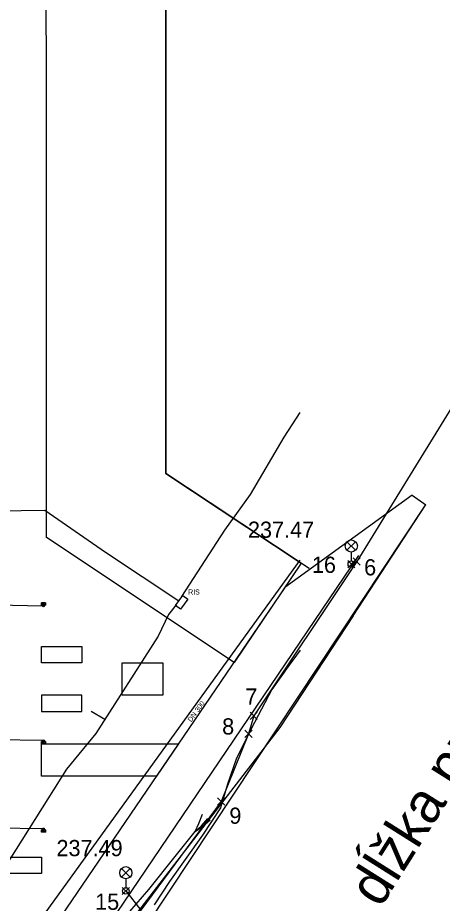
# Model space of a CAD drawing. Extents: x -263861 to -263441, y -1242367 to -1242070.
# Drawn here: x -263784.9 to -263732.4, y -1242254.1 to -1242144.8 of the extents above; entities that cross this region are included whole.
import ezdxf

# ---------------------------------------------------------------- set-up
doc = ezdxf.new("R2010")
doc.units = 0
for name, color, linetype in [('KFA_BODY', 7, 'Continuous'), ('KFA_JESTV_IS_DSP', 7, 'Continuous'), ('KFA_SITUACIA_DSP', 7, 'Continuous'), ('KFA_VO_prelozka_pri_vjazde_do KFA_LAMPA', 7, 'Continuous'), ('KFA_VO_prelozka_pri_vjazde_do KFA_TRASA', 7, 'Continuous'), ('POPIS', 7, 'Continuous')]:
    doc.layers.add(name, color=color, linetype=linetype)

msp = doc.modelspace()

# ---------------------------------------------------------------- linework, layer by layer
at = {"layer": 'KFA_BODY'}
for p, q in [((-263744.11, -1242212.66), (-263743.23, -1242211.78)), ((-263743.23, -1242212.66), (-263744.11, -1242211.78)), ((-263743.43, -1242212.34), (-263742.55, -1242211.45)), ((-263742.55, -1242212.34), (-263743.43, -1242211.45)), ((-263743.67, -1242212.22), (-263742.99, -1242211.9)), ((-263743.67, -1242212.22), (-263743.67, -1242212.22)), ((-263742.99, -1242211.9), (-263742.99, -1242211.9)), ((-263756.17, -1242231.37), (-263755.29, -1242230.49)), ((-263755.29, -1242231.37), (-263756.17, -1242230.49)), ((-263755.73, -1242230.93), (-263755.73, -1242230.93)), ((-263756.81, -1242233.59), (-263755.92, -1242232.7)), ((-263755.92, -1242233.59), (-263756.81, -1242232.7)), ((-263756.36, -1242233.15), (-263756.36, -1242233.15)), ((-263760.19, -1242241.96), (-263759.3, -1242241.07)), ((-263759.3, -1242241.96), (-263760.19, -1242241.07)), ((-263759.75, -1242241.52), (-263759.75, -1242241.52)), ((-263771.97, -1242252.99), (-263771.08, -1242252.11)), ((-263771.08, -1242252.99), (-263771.97, -1242252.11)), ((-263771.53, -1242252.55), (-263771.53, -1242252.55))]:
    msp.add_line(p, q, dxfattribs=at)
at = {"layer": 'KFA_JESTV_IS_DSP'}
for p, q in [((-263751.97, -1242196.56), (-263750, -1242193.5)), ((-263756.14, -1242203.63), (-263751.97, -1242196.56)), ((-263759.28, -1242208.01), (-263756.14, -1242203.63)), ((-263808.34, -1242205.95), (-263781.54, -1242205.56)), ((-263781.54, -1242205.56), (-263774.03, -1242210.74)), ((-263764.6, -1242216.21), (-263759.28, -1242208.01)), ((-263774.03, -1242210.74), (-263764.98, -1242216.74)), ((-263806.91, -1242290.43), (-263750, -1242211.71)), ((-263765.39, -1242217.3), (-263764.49, -1242216.1)), ((-263764.49, -1242216.1), (-263763.89, -1242216.54)), ((-263765.31, -1242217.22), (-263766.27, -1242218.42)), ((-263764.79, -1242217.75), (-263765.39, -1242217.3)), ((-263765.39, -1242217.3), (-263765.39, -1242217.3)), ((-263763.89, -1242216.54), (-263764.79, -1242217.75)), ((-263766.27, -1242218.42), (-263767.52, -1242221.09)), ((-263767.52, -1242221.09), (-263775.23, -1242233.12)), ((-263750, -1242222.85), (-263751.46, -1242224.83)), ((-263751.46, -1242224.83), (-263753.47, -1242227.7)), ((-263753.47, -1242227.7), (-263756.03, -1242232.54)), ((-263774.12, -1242231.39), (-263775.8, -1242230.38)), ((-263756.03, -1242232.54), (-263757.88, -1242236.29)), ((-263775.23, -1242233.12), (-263778.87, -1242237.51)), ((-263757.88, -1242236.29), (-263758.95, -1242239.35)), ((-263778.87, -1242237.51), (-263787.86, -1242251.77)), ((-263758.95, -1242239.35), (-263759.83, -1242242.28)), ((-263759.83, -1242242.28), (-263762.06, -1242245.68)), ((-263762.52, -1242244.22), (-263762.07, -1242243.09)), ((-263762.95, -1242245.22), (-263762.52, -1242244.22)), ((-263762.95, -1242245.22), (-263762.18, -1242244.51)), ((-263762.95, -1242245.22), (-263762.02, -1242244.55)), ((-263762.18, -1242244.51), (-263761.39, -1242243.59)), ((-263762.02, -1242244.55), (-263761.13, -1242243.76)), ((-263762.06, -1242245.68), (-263766.13, -1242251.37)), ((-263765.43, -1242248.29), (-263762.95, -1242245.22)), ((-263768.68, -1242252.39), (-263765.43, -1242248.29)), ((-263766.13, -1242251.37), (-263768.04, -1242254.28)), ((-263771.82, -1242255.98), (-263768.68, -1242252.39))]:
    msp.add_line(p, q, dxfattribs=at)
at = {"layer": 'KFA_SITUACIA_DSP'}
for p, q in [((-263766.58, -1242144.85), (-263766.58, -1242074.39)), ((-263766.58, -1242201.01), (-263766.58, -1242144.85)), ((-263758.42, -1242206.43), (-263766.58, -1242201.01)), ((-263736.13, -1242203.7), (-263751.89, -1242215.1)), ((-263736.13, -1242203.7), (-263734.47, -1242204.91)), ((-263822.88, -1242337.91), (-263734.49, -1242204.94)), ((-263757.19, -1242207.25), (-263758.42, -1242206.43)), ((-263748.89, -1242212.77), (-263757.19, -1242207.25)), ((-263794.9, -1242288.03), (-263742.74, -1242211.14)), ((-263798.9, -1242284.13), (-263751.86, -1242215.08)), ((-263751.89, -1242215.1), (-263751.89, -1242215.1)), ((-263781.82, -1242217.38), (-263790.41, -1242217.22)), ((-263781.97, -1242216.99), (-263781.47, -1242216.99)), ((-263781.97, -1242217.28), (-263781.97, -1242216.99)), ((-263781.97, -1242216.99), (-263781.47, -1242217.28)), ((-263781.97, -1242216.99), (-263781.47, -1242217.28)), ((-263781.47, -1242216.99), (-263781.97, -1242216.99)), ((-263781.47, -1242217.28), (-263781.97, -1242217.28)), ((-263781.47, -1242216.99), (-263781.47, -1242217.28)), ((-263781.47, -1242217.28), (-263781.47, -1242216.99)), ((-263743.42, -1242218.61), (-263752.52, -1242232.37)), ((-263781.97, -1242228.38), (-263781.97, -1242230.38)), ((-263776.97, -1242228.38), (-263781.97, -1242228.38)), ((-263776.97, -1242230.38), (-263776.97, -1242228.38)), ((-263781.97, -1242230.38), (-263776.97, -1242230.38)), ((-263752.52, -1242232.37), (-263782.17, -1242270.82)), ((-263781.82, -1242233.99), (-263790.71, -1242233.83)), ((-263781.97, -1242234.09), (-263781.47, -1242234.09)), ((-263781.97, -1242234.38), (-263781.97, -1242234.09)), ((-263781.97, -1242234.09), (-263781.47, -1242234.38)), ((-263781.97, -1242234.09), (-263781.47, -1242234.38)), ((-263781.47, -1242234.09), (-263781.97, -1242234.09)), ((-263781.47, -1242234.38), (-263781.97, -1242234.38)), ((-263781.97, -1242234.38), (-263771.97, -1242234.38)), ((-263781.97, -1242238.38), (-263781.97, -1242234.38)), ((-263781.97, -1242234.38), (-263781.97, -1242234.38)), ((-263781.47, -1242234.09), (-263781.47, -1242234.38)), ((-263781.47, -1242234.38), (-263781.47, -1242234.09)), ((-263771.97, -1242234.38), (-263765.01, -1242234.38)), ((-263765.01, -1242234.38), (-263767.74, -1242238.38)), ((-263771.97, -1242238.38), (-263781.97, -1242238.38)), ((-263767.74, -1242238.38), (-263771.97, -1242238.38)), ((-263781.82, -1242244.89), (-263790.91, -1242244.72)), ((-263781.97, -1242244.99), (-263781.47, -1242244.99)), ((-263781.97, -1242245.28), (-263781.97, -1242244.99)), ((-263781.97, -1242244.99), (-263781.47, -1242245.28)), ((-263781.97, -1242244.99), (-263781.47, -1242245.28)), ((-263781.47, -1242244.99), (-263781.97, -1242244.99)), ((-263781.47, -1242245.28), (-263781.97, -1242245.28)), ((-263781.47, -1242244.99), (-263781.47, -1242245.28)), ((-263781.47, -1242245.28), (-263781.47, -1242244.99))]:
    msp.add_line(p, q, dxfattribs=at)
for points in [[(-263766.58, -1242083.48), (-263766.58, -1242201.01), (-263749.88, -1242212.11), (-263758.15, -1242224.37), (-263781.36, -1242208.94), (-263781.37, -1242084.9)], [(-263781.97, -1242222.38), (-263776.97, -1242222.38), (-263776.97, -1242224.38), (-263781.97, -1242224.38)], [(-263771.97, -1242224.38), (-263766.97, -1242224.38), (-263766.97, -1242228.38), (-263771.97, -1242228.38)], [(-263786.97, -1242248.38), (-263781.97, -1242248.38), (-263781.97, -1242250.38), (-263786.97, -1242250.38)]]:
    msp.add_lwpolyline(points, close=True, dxfattribs=at)
msp.add_lwpolyline([(-263743.42, -1242218.61), (-263734.49, -1242204.94), (-263734.47, -1242204.91), (-263734.47, -1242204.91)], dxfattribs=at)
for centre in [(-263781.72, -1242217.38), (-263781.72, -1242233.99), (-263781.72, -1242244.89)]:
    msp.add_circle(centre, 0.1, dxfattribs=at)
at = {"layer": 'KFA_VO_prelozka_pri_vjazde_do KFA_LAMPA'}
for p, q in [((-263744.2, -1242210.5), (-263743.14, -1242209.44)), ((-263744.2, -1242209.44), (-263743.14, -1242210.5)), ((-263743.67, -1242210.72), (-263743.67, -1242211.82)), ((-263772.06, -1242250.83), (-263771, -1242249.77)), ((-263772.06, -1242249.77), (-263771, -1242250.83)), ((-263771.53, -1242251.05), (-263771.53, -1242252.15))]:
    msp.add_line(p, q, dxfattribs=at)
for centre, radius in [((-263743.67, -1242209.97), 0.75), ((-263743.67, -1242212.22), 0.4), ((-263771.53, -1242250.3), 0.75), ((-263771.53, -1242252.55), 0.4)]:
    msp.add_circle(centre, radius, dxfattribs=at)
at = {"layer": 'KFA_VO_prelozka_pri_vjazde_do KFA_TRASA'}
msp.add_line((-263771.53, -1242252.55), (-263769.7, -1242254.93), dxfattribs=at)
msp.add_lwpolyline([(-263678.35, -1242101.42), (-263696.56, -1242141.18), (-263711.21, -1242160.53), (-263718.89, -1242173.72), (-263725.97, -1242184.27), (-263742.99, -1242211.9), (-263755.73, -1242230.93), (-263756.36, -1242233.15), (-263759.75, -1242241.52), (-263769.7, -1242254.93), (-263792.51, -1242289.19), (-263819.79, -1242330.66), (-263820.54, -1242331.86)], dxfattribs=at)

# ---------------------------------------------------------------- texts
at = {"layer": 'KFA_BODY'}
for s, p in [('237.47', (-263756.44, -1242208.96)), ('16', (-263748.54, -1242213.29)), ('6', (-263742.08, -1242213.6)), ('7', (-263756.77, -1242229.56)), ('8', (-263759.63, -1242233.24)), ('9', (-263758.74, -1242244.26)), ('237.49', (-263780.11, -1242248.26)), ('15', (-263775.33, -1242254.88))]:
    msp.add_text(s, height=2, dxfattribs=at).set_placement(p)
at = {"layer": 'KFA_JESTV_IS_DSP'}
msp.add_text('RIS', height=0.625, dxfattribs=at).set_placement((-263763.83, -1242215.96))
msp.add_text(' DN 300', height=0.625, rotation=54.0559, dxfattribs=at).set_placement((-263763.59, -1242231.95))
at = {"layer": 'POPIS'}
msp.add_text('trasa VO, dĺžka preložky - 271,57 m', height=5, rotation=57.838, dxfattribs=at).set_placement((-263756.08, -1242280.23))

doc.saveas('drawing.dxf')
